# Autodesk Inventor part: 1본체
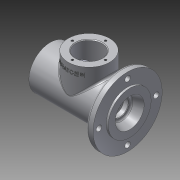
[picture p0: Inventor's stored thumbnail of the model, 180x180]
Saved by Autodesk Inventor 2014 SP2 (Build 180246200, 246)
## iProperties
Created: 2016-08
Part Number: 1본체
Material: 알루미늄 6061
Document SubType Name: Modeling
Designer: 달림반
Density: 2.71 g/cm^3
Appearance: 알루미늄 - 평지
Mass: 765.639 g
Surface Area: 620.528 cm^2
Volume: 282.524 cm^3
Author: 달림반
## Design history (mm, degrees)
sketch "스케치1"
  geometry: L1 (0, 0)-(115, 0); L2 (0, 21)-(9, 21); L3 (9, 21)-(9, 24); L4 (9, 24)-(12, 24); L5 (12, 24)-(12, 20); L6 (12, 20)-(21, 20); L7 (21, 20)-(21, 17.5); L8 (21, 17.5)-(24.25, 17.5); L9 (24.25, 17.5)-(24.25, 18.5); L10 (24.25, 18.5)-(26, 18.5); L11 (26, 18.5)-(26, 17.5); L12 (26, 17.5)-(37, 17.5); L13 (37, 17.5)-(37, 26); L14 (37, 26)-(75, 26); L15 (75, 26)-(75, 17.5); L16 (75, 17.5)-(86, 17.5); L17 (86, 17.5)-(86, 16.5); L18 (86, 16.5)-(91, 16.5); L19 (91, 16.5)-(91, 10); L20 (91, 10)-(93.7, 10); L21 (93.7, 10)-(93.7, 12.5); L22 (93.7, 12.5)-(101, 12.5); L23 (101, 12.5)-(101, 16); L24 (101, 16)-(115, 21); L25 (115, 21)-(115, 31); L26 (115, 31)-(112, 31); L27 (112, 31)-(112, 50); L28 (112, 50)-(102, 50); L29 (102, 50)-(102, 31); L30 (102, 31)-(0, 31); L31 (0, 31)-(0, 21)
  constraints: 62 end point, 28 parallel, 2 vertical alignment, 1 collinear, 1 horizontal, 1 perpendicular
  dimensions: "d0" = 115 distance between parallel lines of L25 L31; "d1" = 3 distance of L25.end L26.end; "d3" = 100 diameter of L28 L1; "d4" = 62 diameter of L26 L1; "d5" = 42 diameter of L24.end L1; "d6" = 32 diameter of L23.end L1; "d7" = 25 diameter of L22 L1; "d8" = 20 diameter of L20 L1; "d9" = 33 diameter of L18 L1; "d10" = 35 diameter of L16 L1; "d11" = 52 diameter of L14 L1; "d12" = 35 diameter of L12 L1; "d13" = 37 diameter of L10 L1; "d14" = 35 diameter of L8 L1; "d15" = 40 diameter of L6 L1; "d16" = 48 diameter of L4 L1; "d17" = 42 diameter of L2 L1; "d18" = 62 diameter of L30 L1; "d19" = 14 distance between parallel lines of L25 L23; "d20" = 2.7 distance of L19.end L20.end; "d21" = 7.3 distance of L21.end L22.end; "d22" = 38 distance of L13.end L14.end; "d23" = 3 distance of L4.end L3.end; "d24" = 12 distance between parallel lines of L5 L31; "d25" = 21 distance between parallel lines of L7 L31; "d26" = 26 distance between parallel lines of L31 L11; "d27" = 1.75 distance of L9.end L10.end; "d28" = 5 distance between parallel lines of L17 L19; "d88" = 13 distance between parallel lines of L25 L29
revolve "회전1" sketch "스케치1" stored, may be unused: angle "d29" = 90 deg
chamfer "모따기1" distance "d38" = 1; stored, may be unused: second distance "d39" = 2, angle "d40" = 45 deg
node "작업 평면1"
sketch "스케치7"
  geometry: C1 r 30 at (-56, 0); C2 r 19 at (-56, 0); 1 further point
  constraints: 2 centre point, 1 coincident, 1 horizontal alignment
  dimensions: "d43" = 60 diameter of C1; "d44" = 56 distance of point (0, 0) C1.centre; "d45" = 38 diameter of C2
extrude "돌출2" join sketch "스케치7" stored distance "d46" = 40; taper "d47" = 0 deg
sketch "스케치8"
  geometry: C1 r 19 at (0, 0) reference; 1 further point
extrude "돌출3" cut sketch "스케치8" distance "d48" = 40; taper "d49" = 0 deg
chamfer "모따기2" distance "d50" = 1; stored, may be unused: second distance "d51" = 2, angle "d52" = 45 deg
feature "스레드1" dims "d53" = 10, "d54" = 0
chamfer "모따기3" distance "d55" = 1; stored, may be unused: second distance "d56" = 2, angle "d57" = 45 deg
sketch "스케치9"
  geometry: C1 r 30 at (0, 0) reference; C2 r 20 at (0, 0) reference; A1 r 24 centre (0, 0) between (0, 24) and (24, 0); 3 further points
  constraints: 4 point on circle, 2 horizontal alignment, 2 vertical alignment, 1 centre point, 1 coincident
  dimensions: "d58" = 48 diameter of A1
hole "구멍1" sketch "스케치9" at (0, 24), (24, 0), (0, -24), (-24, 0) diameter "d59" = 3.242; stored, may be unused: countersink angle "d63" = 90 deg, drill point angle "d65" = 118 deg; dims "d60" = 8, "d61" = 4, "d62" = 2, "d64" = 10
sketch "스케치10"
  geometry: C1 r 50 at (0, 0) reference; C2 r 31 at (0, 0) reference; A1 r 41.5 centre (0, 0) between (0, 41.5) and (41.5, 0); 2 further points
  constraints: 4 point on circle, 2 horizontal alignment, 2 vertical alignment, 1 centre point, 1 coincident
  dimensions: "d66" = 83 diameter of A1
hole "구멍2" sketch "스케치10" at (0, 41.5), (41.5, 0), (0, -41.5), (-41.5, 0) diameter "d67" = 8; stored, may be unused: countersink angle "d71" = 90 deg, drill point angle "d73" = 118 deg; dims "d68" = 8, "d69" = 4, "d70" = 2, "d72" = 20
sketch "스케치11"
  geometry: L1 (101, 12.904)-(100.3, 12.5); L2 (101, 12.5)-(93.7, 12.5) reference; L3 (101, -16)-(101, 16) reference; L4 (0, 0)-(60.979, 0)
  constraints: 4 end point, 2 point on line, 1 perpendicular
  dimensions: "d74" = 30 deg angle of L2 L1; "d75" = 0.7 distance from line of L3 L1.end
revolve "회전3" sketch "스케치11" stored, may be unused: angle "d76" = 90 deg
fillet "모깎기1" dims "d77" = 0.3
fillet "모깎기2" dims "d78" = 3
fillet "모깎기3" dims "d79" = 3
fillet "모깎기4" dims "d80" = 3
node "작업 평면2"
sketch "스케치13"
  geometry: L1 (0, -31)-(0, 31) reference; L2 (26, 49)-(86, 49) reference; 2 further points
  constraints: 1 other
  dimensions: "d82" = 56 distance from line of L1 point (56, 39); "d83" = 10 distance from line of L2 point (56, 39)
feature "엠보싱1" sketch "스케치13" dims "d84" = 0.5, "d85" = 0
fillet "모깎기6" dims "d87" = 3
node "솔리드1"
other parameters: "d42" = 49, "d81" = 84.75
